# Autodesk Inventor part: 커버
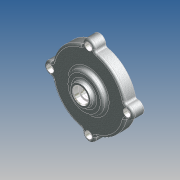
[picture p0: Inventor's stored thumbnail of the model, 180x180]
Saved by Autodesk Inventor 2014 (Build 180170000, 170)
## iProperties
Company: 한국ATC센터
Created: 2012-05
Part Number: 커버
Document SubType Name: 모델링
Designer: KYOUNG IL JANG
Mass: 196.659 g
Surface Area: 278.607 cm^2
Volume: 72.5678 cm^3
Density: 2.71 g/cm^3
Material: 알루미늄-6061
Appearance: 알루미늄 캐스트
변환 표준: STEP AP214IS
파일 이름: C:\Users\SeoGD\Desktop\?쒗뿕\而ㅻ쾭-1.stp
전처리기: Build: 253, Release: 2010 SP1 - Date: Wed 07/29/2009
전송 단위: 밀리미터
불확실성: 0.01
Author: KYOUNG IL JANG
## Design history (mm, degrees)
sketch "스케치1"
  geometry: L1 (0, 0)-(0, 26); L2 (50, 0)-(50, 15); L3 (50, 15)-(25, 15); L4 (25, 15)-(25, 21); L5 (25, 21)-(15, 21); L6 (15, 21)-(13.66, 26); L7 (13.66, 26)-(10, 26); L8 (50, 0)-(45, 0); L9 (45, 0)-(45, 10); L10 (45, 10)-(14.5, 10); L11 (14.5, 10)-(13.266, 3); L12 (13.266, 3)-(11, 3); L13 (11, 3)-(11, 16); L14 (11, 16)-(7.5, 16); L15 (7.5, 16)-(7.5, 19); L16 (7.5, 19)-(10, 19); L17 (10, 19)-(10, 26)
  constraints: 34 end point, 10 parallel, 2 perpendicular, 2 point on line, 1 vertical
  dimensions: "d11" = 100 diameter of L2 L1; "d12" = 22 diameter of L13 L1; "d13" = 90 diameter of L9 L1; "d14" = 15 distance between parallel lines of L3 L8; "d15" = 10 distance between parallel lines of L8 L10; "d16" = 29 diameter of L10.end L1; "d17" = 100 deg angle of L11 L10; "d18" = 7 distance between parallel lines of L12 L10; "d19" = 13 distance between parallel lines of L14 L12; "d20" = 3 distance between parallel lines of L16 L14; "d21" = 15 diameter of L15 L1; "d22" = 20 diameter of L17 L1; "d23" = 30 diameter of L5.end L1; "d24" = 6 distance between parallel lines of L5 L3; "d25" = 50 diameter of L4 L1; "d26" = 105 deg angle of L5 L6; "d50" = 26 distance of L1.start L1.end
revolve "회전1" sketch "스케치1" stored, may be unused: angle "d27" = 90 deg
sketch "스케치2" dims "d29" = 104
  geometry: A1 r 8.5 centre (0, 52) between (8.074, 49.344) and (-8.074, 49.344); A2 r 50 centre (0, 0) between (-8.074, 49.344) and (8.074, 49.344) reference; 2 further points
  constraints: 4 point on circle, 2 vertical alignment, 1 centre point, 1 coincident, 2 other
  dimensions: "d28" = 17 diameter of A1
extrude "돌출1" join sketch "스케치2" stored distance "d30" = 10; taper "d31" = 0 deg
fillet "모깎기3" dims "d32" = 3
fillet "모깎기4" dims "d45" = 3, "d46" = 0.2
chamfer "모따기1" distance "d47" = 1; stored, may be unused: second distance "d48" = 2, angle "d49" = 45 deg
hole "구멍2" diameter "d38" = 5.5; stored, may be unused: countersink angle "d42" = 90 deg, drill point angle "d44" = 118 deg; dims "d36" = 10, "d37" = 10, "d39" = 6, "d40" = 9.5, "d41" = 5.4, "d43" = 8
node "솔리드1"
node "솔리드 본체"
node "곡면 본체"
pattern_circular "원형 패턴1" dims angle "d34" = 360 deg
pattern_circular "원형 패턴2" dims angle "d52" = 360 deg
node "솔리드2"
